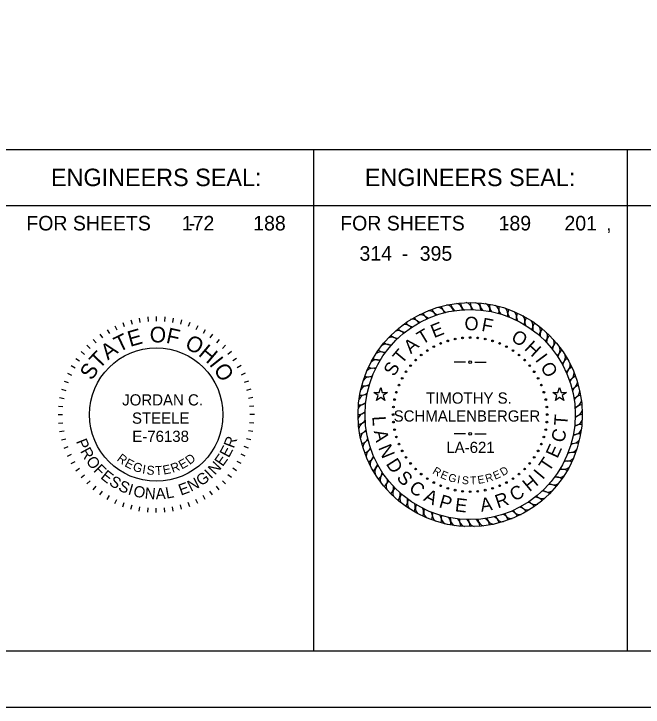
# Model space of a CAD drawing. Extents: x -42.2 to 34, y 0 to 22.
# Drawn here: x 16.1 to 21.71, y 0 to 6.19 of the extents above; entities that cross this region are included whole.
import ezdxf

# ---------------------------------------------------------------- set-up
doc = ezdxf.new("R2010")
doc.units = 0
for name, color, linetype in [('SH_Border', 7, 'Continuous'), ('SH_Cut_Line', 7, 'Continuous'), ('SH_Data', 7, 'Continuous')]:
    doc.layers.add(name, color=color, linetype=linetype)

msp = doc.modelspace()

# ---------------------------------------------------------------- linework, layer by layer
at = {"layer": 'SH_Border'}
msp.add_lwpolyline([(2, 21.5), (33.5, 21.5), (33.5, 0.5), (2, 0.5)], close=True, dxfattribs=at)
at = {"layer": 'SH_Cut_Line'}
msp.add_lwpolyline([(0, 0), (34, 0), (34, 22), (0, 22)], close=True, dxfattribs=at)
at = {"layer": 'SH_Data'}
for p, q in [((15.9739, 4.977), (18.7739, 4.977)), ((18.7739, 0.5), (18.7739, 4.977)), ((18.7739, 4.977), (21.5739, 4.977)), ((21.5739, 0.5), (21.5739, 4.977)), ((21.5739, 4.977), (24.3739, 4.977)), ((15.9739, 4.477), (18.7739, 4.477)), ((18.7739, 4.477), (21.5739, 4.477)), ((21.5739, 4.477), (24.3739, 4.477)), ((17.2172, 3.4721), (17.2242, 3.4327)), ((17.2929, 3.4821), (17.2964, 3.4422)), ((17.3692, 3.4854), (17.3692, 3.4454)), ((17.4454, 3.4821), (17.442, 3.4422)), ((17.5211, 3.4721), (17.5142, 3.4327)), ((16.9994, 3.4034), (17.0163, 3.3672)), ((17.0699, 3.4326), (17.0836, 3.395)), ((17.1427, 3.4556), (17.1531, 3.4169)), ((17.5957, 3.4556), (17.5853, 3.4169)), ((17.6685, 3.4326), (17.6548, 3.395)), ((17.739, 3.4034), (17.7221, 3.3672)), ((16.9317, 3.3682), (16.9517, 3.3335)), ((17.8067, 3.3682), (17.7867, 3.3335)), ((16.8067, 3.2807), (16.8325, 3.25)), ((16.8673, 3.3272), (16.8903, 3.2944)), ((17.8711, 3.3272), (17.8481, 3.2944)), ((17.9316, 3.2807), (17.9059, 3.25)), ((16.7505, 3.2291), (16.7788, 3.2008)), ((17.9879, 3.2291), (17.9596, 3.2008)), ((16.6989, 3.1728), (16.7295, 3.1471)), ((18.0395, 3.1728), (18.0088, 3.1471)), ((16.6524, 3.1123), (16.6852, 3.0893)), ((18.0859, 3.1123), (18.0532, 3.0893)), ((16.6114, 3.0479), (16.6461, 3.0279)), ((18.127, 3.0479), (18.0923, 3.0279)), ((20.1267, 3.0779), (20.0267, 3.0779)), ((20.2117, 3.0779), (20.3117, 3.0779)), ((16.5762, 2.9802), (16.6124, 2.9633)), ((18.1622, 2.9802), (18.126, 2.9633)), ((16.547, 2.9097), (16.5845, 2.896)), ((18.1914, 2.9097), (18.1538, 2.896)), ((16.524, 2.8369), (16.5626, 2.8265)), ((18.2144, 2.8369), (18.1757, 2.8265)), ((16.5075, 2.7623), (16.5469, 2.7554)), ((18.2309, 2.7623), (18.1915, 2.7554)), ((16.4975, 2.6867), (16.5374, 2.6832)), ((18.2409, 2.6867), (18.201, 2.6832)), ((16.4942, 2.6104), (16.5342, 2.6104)), ((18.2442, 2.6104), (18.2042, 2.6104)), ((16.4975, 2.5341), (16.5374, 2.5376)), ((18.2409, 2.5341), (18.201, 2.5376)), ((16.5075, 2.4585), (16.5469, 2.4654)), ((18.2309, 2.4585), (18.1915, 2.4654)), ((20.1267, 2.4379), (20.0267, 2.4379)), ((20.2117, 2.4379), (20.3117, 2.4379)), ((16.524, 2.3839), (16.5626, 2.3943)), ((18.2144, 2.3839), (18.1757, 2.3943)), ((16.547, 2.3111), (16.5845, 2.3248)), ((18.1914, 2.3111), (18.1538, 2.3248)), ((16.5762, 2.2406), (16.6124, 2.2575)), ((18.1622, 2.2406), (18.126, 2.2575)), ((16.6114, 2.1729), (16.6461, 2.1929)), ((18.127, 2.1729), (18.0923, 2.1929)), ((16.6524, 2.1085), (16.6852, 2.1315)), ((18.0859, 2.1085), (18.0532, 2.1315)), ((16.6989, 2.048), (16.7295, 2.0737)), ((18.0395, 2.048), (18.0088, 2.0737)), ((16.7505, 1.9917), (16.7788, 2.02)), ((17.9879, 1.9917), (17.9596, 2.02)), ((16.8067, 1.9401), (16.8325, 1.9707)), ((16.8673, 1.8936), (16.8903, 1.9264)), ((17.8711, 1.8936), (17.8481, 1.9264)), ((17.9316, 1.9401), (17.9059, 1.9707)), ((16.9317, 1.8526), (16.9517, 1.8873)), ((17.8067, 1.8526), (17.7867, 1.8873)), ((16.9994, 1.8174), (17.0163, 1.8536)), ((17.0699, 1.7882), (17.0836, 1.8258)), ((17.1427, 1.7652), (17.1531, 1.8038)), ((17.5957, 1.7652), (17.5853, 1.8038)), ((17.6685, 1.7882), (17.6548, 1.8258)), ((17.739, 1.8174), (17.7221, 1.8536)), ((17.2172, 1.7487), (17.2242, 1.7881)), ((17.2929, 1.7387), (17.2964, 1.7786)), ((17.3692, 1.7354), (17.3692, 1.7754)), ((17.4454, 1.7387), (17.442, 1.7786)), ((17.5211, 1.7487), (17.5142, 1.7881))]:
    msp.add_line(p, q, dxfattribs=at)
for points in [[(19.3097, 2.8073), (19.3566, 2.8073), (19.3711, 2.8519), (19.3856, 2.8073), (19.4324, 2.8073), (19.3946, 2.7797), (19.409, 2.7351), (19.3711, 2.7627), (19.3331, 2.7351), (19.3476, 2.7797)], [(20.9059, 2.8073), (20.9528, 2.8073), (20.9673, 2.8519), (20.9818, 2.8073), (21.0287, 2.8073), (20.9908, 2.7797), (21.0053, 2.7351), (20.9673, 2.7627), (20.9293, 2.7351), (20.9438, 2.7797)]]:
    msp.add_lwpolyline(points, close=True, dxfattribs=at)
for centre, radius in [((20.1692, 2.6104), 1), ((20.1692, 2.6104), 0.9375), ((20.0351, 3.2847), 0.0075), ((20.1018, 3.2946), 0.0075), ((20.1692, 3.2979), 0.0075), ((20.2366, 3.2946), 0.0075), ((20.3033, 3.2847), 0.0075), ((19.8451, 3.2167), 0.0075), ((19.9061, 3.2456), 0.0075), ((19.9696, 3.2683), 0.0075), ((20.3688, 3.2683), 0.0075), ((20.4323, 3.2456), 0.0075), ((20.4933, 3.2167), 0.0075), ((17.3692, 2.6104), 0.595), ((19.7872, 3.182), 0.0075), ((20.5511, 3.182), 0.0075), ((19.6831, 3.0965), 0.0075), ((19.733, 3.1418), 0.0075), ((20.6053, 3.1418), 0.0075), ((20.6553, 3.0965), 0.0075), ((19.6377, 3.0465), 0.0075), ((20.1692, 3.0779), 0.0125), ((20.7006, 3.0465), 0.0075), ((19.5976, 2.9923), 0.0075), ((20.7408, 2.9923), 0.0075), ((19.5629, 2.9345), 0.0075), ((20.7755, 2.9345), 0.0075), ((19.534, 2.8735), 0.0075), ((20.8044, 2.8735), 0.0075), ((19.5113, 2.81), 0.0075), ((20.8271, 2.81), 0.0075), ((19.4949, 2.7445), 0.0075), ((20.8435, 2.7445), 0.0075), ((19.485, 2.6778), 0.0075), ((20.8534, 2.6778), 0.0075), ((19.4817, 2.6104), 0.0075), ((20.8567, 2.6104), 0.0075), ((19.485, 2.543), 0.0075), ((20.8534, 2.543), 0.0075), ((19.4949, 2.4763), 0.0075), ((20.8435, 2.4763), 0.0075), ((19.5113, 2.4108), 0.0075), ((20.1692, 2.4379), 0.0125), ((20.8271, 2.4108), 0.0075), ((19.534, 2.3473), 0.0075), ((20.8044, 2.3473), 0.0075), ((19.5629, 2.2863), 0.0075), ((20.7755, 2.2863), 0.0075), ((19.5976, 2.2284), 0.0075), ((20.7408, 2.2284), 0.0075), ((19.6377, 2.1742), 0.0075), ((20.7006, 2.1742), 0.0075), ((19.6831, 2.1243), 0.0075), ((20.6553, 2.1243), 0.0075), ((19.733, 2.0789), 0.0075), ((19.7872, 2.0388), 0.0075), ((20.5511, 2.0388), 0.0075), ((20.6053, 2.0789), 0.0075), ((19.8451, 2.0041), 0.0075), ((19.9061, 1.9752), 0.0075), ((20.4323, 1.9752), 0.0075), ((20.4933, 2.0041), 0.0075), ((19.9696, 1.9525), 0.0075), ((20.0351, 1.9361), 0.0075), ((20.1018, 1.9262), 0.0075), ((20.1692, 1.9229), 0.0075), ((20.2366, 1.9262), 0.0075), ((20.3033, 1.9361), 0.0075), ((20.3688, 1.9525), 0.0075)]:
    msp.add_circle(centre, radius, dxfattribs=at)
for centre, radius, start, end in [((19.9567, 3.5235), 0.065, 11.11471, 86.62222), ((20.0792, 3.61), 0.085, 190, 237.74501), ((20.0371, 3.5385), 0.065, 6.11471, 81.62222), ((20.1667, 3.614), 0.085, 185, 232.74501), ((20.1185, 3.5465), 0.065, 1.11471, 76.62222), ((20.2542, 3.6104), 0.085, 180, 227.74501), ((20.2002, 3.5474), 0.065, 356.11471, 71.62222), ((20.341, 3.5992), 0.085, 175, 222.74501), ((20.2818, 3.5411), 0.065, 351.11471, 66.62222), ((20.4265, 3.5804), 0.085, 170, 217.74501), ((19.8014, 3.4727), 0.065, 21.11471, 96.62222), ((19.907, 3.5792), 0.085, 200, 247.74501), ((19.8779, 3.5015), 0.065, 16.11471, 91.62222), ((19.9925, 3.5983), 0.085, 195, 242.74501), ((20.3625, 3.5278), 0.065, 346.11471, 61.62222), ((20.5101, 3.5543), 0.085, 165, 212.74501), ((20.4417, 3.5074), 0.065, 341.11471, 56.62222), ((20.5911, 3.521), 0.085, 160, 207.74501), ((20.5188, 3.4802), 0.065, 336.11471, 51.62222), ((19.7428, 3.5189), 0.085, 210, 257.74501), ((19.7276, 3.4374), 0.065, 26.11471, 101.62222), ((19.8236, 3.5526), 0.085, 205, 252.74501), ((20.6688, 3.4808), 0.085, 155, 202.74501), ((20.5933, 3.4465), 0.065, 331.11471, 46.62222), ((20.7428, 3.4339), 0.085, 150, 197.74501), ((19.5907, 3.3481), 0.065, 36.11471, 111.62222), ((19.6652, 3.4783), 0.085, 215, 262.74501), ((19.6572, 3.3957), 0.065, 31.11471, 106.62222), ((20.6646, 3.4063), 0.065, 326.11471, 41.62222), ((20.8124, 3.3808), 0.085, 145, 192.74501), ((19.5286, 3.2949), 0.065, 41.11471, 116.62222), ((19.5915, 3.4311), 0.085, 220, 267.74501), ((20.7321, 3.3601), 0.065, 321.11471, 36.62222), ((20.8771, 3.3218), 0.085, 140, 187.74501), ((20.7953, 3.3082), 0.065, 316.11471, 31.62222), ((19.4714, 3.2365), 0.065, 46.11471, 121.62222), ((19.5222, 3.3776), 0.085, 225, 272.74501), ((20.9364, 3.2574), 0.085, 135, 182.74501), ((20.8537, 3.251), 0.065, 311.11471, 26.62222), ((19.4195, 3.1733), 0.065, 51.11471, 126.62222), ((19.4578, 3.3183), 0.085, 230, 277.74501), ((20.9899, 3.1881), 0.085, 130, 177.74501), ((19.3733, 3.1058), 0.065, 56.11471, 131.62222), ((19.3988, 3.2536), 0.085, 235, 282.74501), ((20.9069, 3.1889), 0.065, 306.11471, 21.62222), ((21.0371, 3.1143), 0.085, 125, 172.74501), ((19.3331, 3.0345), 0.065, 61.11471, 136.62222), ((19.3457, 3.184), 0.085, 240, 287.74501), ((20.9545, 3.1224), 0.065, 301.11471, 16.62222), ((21.0777, 3.0368), 0.085, 120, 167.74501), ((19.2988, 3.11), 0.085, 245, 292.74501), ((20.9962, 3.052), 0.065, 296.11471, 11.62222), ((21.1114, 2.956), 0.085, 115, 162.74501), ((19.2993, 2.96), 0.065, 66.11471, 141.62222), ((21.0315, 2.9782), 0.065, 291.11471, 6.62222), ((19.2722, 2.8829), 0.065, 71.11471, 146.62222), ((19.2586, 3.0323), 0.085, 250, 297.74501), ((21.138, 2.8725), 0.085, 110, 157.74501), ((19.2518, 2.8037), 0.065, 76.11471, 151.62222), ((19.2253, 2.9513), 0.085, 255, 302.74501), ((21.0603, 2.9017), 0.065, 286.11471, 1.62222), ((21.1571, 2.7871), 0.085, 105, 152.74501), ((19.2385, 2.723), 0.065, 81.11471, 156.62222), ((19.1991, 2.8678), 0.085, 260, 307.74501), ((21.0823, 2.8229), 0.065, 281.11471, 356.62222), ((21.1688, 2.7003), 0.085, 100, 147.74501), ((21.0973, 2.7425), 0.065, 276.11471, 351.62222), ((19.2322, 2.6415), 0.065, 86.11471, 161.62222), ((19.1804, 2.7822), 0.085, 265, 312.74501), ((21.1728, 2.6129), 0.085, 95, 142.74501), ((19.1692, 2.6954), 0.085, 270, 317.74501), ((19.2331, 2.5597), 0.065, 91.11471, 166.62222), ((21.1692, 2.5254), 0.085, 90, 137.74501), ((21.1053, 2.6611), 0.065, 271.11471, 346.62222), ((19.1656, 2.6079), 0.085, 275, 322.74501), ((19.241, 2.4783), 0.065, 96.11471, 171.62222), ((21.1062, 2.5793), 0.065, 266.11471, 341.62222), ((19.1696, 2.5205), 0.085, 280, 327.74501), ((21.158, 2.4386), 0.085, 85, 132.74501), ((19.2561, 2.3979), 0.065, 101.11471, 176.62222), ((21.1392, 2.353), 0.085, 80, 127.74501), ((21.0999, 2.4978), 0.065, 261.11471, 336.62222), ((19.1813, 2.4337), 0.085, 285, 332.74501), ((19.2781, 2.3191), 0.065, 106.11471, 181.62222), ((21.1131, 2.2695), 0.085, 75, 122.74501), ((21.0865, 2.4171), 0.065, 256.11471, 331.62222), ((19.2004, 2.3482), 0.085, 290, 337.74501), ((19.3069, 2.2426), 0.065, 111.11471, 186.62222), ((21.0662, 2.3379), 0.065, 251.11471, 326.62222), ((19.227, 2.2648), 0.085, 295, 342.74501), ((19.3422, 2.1688), 0.065, 116.11471, 191.62222), ((21.0798, 2.1885), 0.085, 70, 117.74501), ((19.2607, 2.184), 0.085, 300, 347.74501), ((21.0396, 2.1107), 0.085, 65, 112.74501), ((21.039, 2.2607), 0.065, 246.11471, 321.62222), ((19.3838, 2.0984), 0.065, 121.11471, 196.62222), ((20.9927, 2.0368), 0.085, 60, 107.74501), ((21.0053, 2.1863), 0.065, 241.11471, 316.62222), ((19.3013, 2.1064), 0.085, 305, 352.74501), ((19.4314, 2.0319), 0.065, 126.11471, 201.62222), ((20.9396, 1.9672), 0.085, 55, 102.74501), ((20.9651, 2.115), 0.065, 236.11471, 311.62222), ((19.3485, 2.0327), 0.085, 310, 357.74501), ((19.4847, 1.9698), 0.065, 131.11471, 206.62222), ((20.8806, 1.9025), 0.085, 50, 97.74501), ((20.9189, 2.0475), 0.065, 231.11471, 306.62222), ((19.402, 1.9634), 0.085, 315, 2.74501), ((19.5431, 1.9126), 0.065, 136.11471, 211.62222), ((20.8162, 1.8432), 0.085, 45, 92.74501), ((20.867, 1.9843), 0.065, 226.11471, 301.62222), ((19.4613, 1.899), 0.085, 320, 7.74501), ((19.6063, 1.8607), 0.065, 141.11471, 216.62222), ((19.526, 1.84), 0.085, 325, 12.74501), ((20.7469, 1.7897), 0.085, 40, 87.74501), ((20.8098, 1.9259), 0.065, 221.11471, 296.62222), ((19.6738, 1.8145), 0.065, 146.11471, 221.62222), ((19.5956, 1.7869), 0.085, 330, 17.74501), ((19.745, 1.7743), 0.065, 151.11471, 226.62222), ((20.6731, 1.7425), 0.085, 35, 82.74501), ((20.7477, 1.8727), 0.065, 216.11471, 291.62222), ((19.6695, 1.74), 0.085, 335, 22.74501), ((19.8195, 1.7405), 0.065, 156.11471, 231.62222), ((19.7473, 1.6998), 0.085, 340, 27.74501), ((19.8967, 1.7134), 0.065, 161.11471, 236.62222), ((20.5148, 1.6682), 0.085, 25, 72.74501), ((20.6108, 1.7834), 0.065, 206.11471, 281.62222), ((20.5956, 1.7019), 0.085, 30, 77.74501), ((20.6812, 1.825), 0.065, 211.11471, 286.62222), ((19.8283, 1.6665), 0.085, 345, 32.74501), ((19.9759, 1.693), 0.065, 166.11471, 241.62222), ((19.9118, 1.6403), 0.085, 350, 37.74501), ((20.0566, 1.6797), 0.065, 171.11471, 246.62222), ((19.9974, 1.6216), 0.085, 355, 42.74501), ((20.1381, 1.6734), 0.065, 176.11471, 251.62222), ((20.0842, 1.6104), 0.085, 360, 47.74501), ((20.2199, 1.6743), 0.065, 181.11471, 256.62222), ((20.1717, 1.6068), 0.085, 5, 52.74501), ((20.3013, 1.6823), 0.065, 186.11471, 261.62222), ((20.2591, 1.6108), 0.085, 10, 57.74501), ((20.3817, 1.6973), 0.065, 191.11471, 266.62222), ((20.3459, 1.6225), 0.085, 15, 62.74501), ((20.4605, 1.7193), 0.065, 196.11471, 271.62222), ((20.4313, 1.6416), 0.085, 20, 67.74501), ((20.537, 1.7481), 0.065, 201.11471, 276.62222)]:
    msp.add_arc(centre, radius, start, end, dxfattribs=at)

# ---------------------------------------------------------------- texts
for s, height, p in [('ENGINEERS SEAL:', 0.156, (16.4298, 4.649)), ('ENGINEERS SEAL:', 0.156, (19.2298, 4.649)), ('FOR SHEETS       -', 0.13, (16.2104, 4.2535)), ('172', 0.13, (17.5972, 4.2535)), ('188', 0.13, (18.2342, 4.2535)), ('FOR SHEETS       -', 0.13, (19.0104, 4.2535)), ('189', 0.13, (20.423, 4.2535)), ('201', 0.13, (21.0103, 4.2535)), (',', 0.13, (21.3824, 4.2535)), ('314', 0.13, (19.182, 3.9835)), ('395', 0.13, (19.7193, 3.9835)), ('-', 0.13, (19.5582, 3.9835)), ('JORDAN C.', 0.1, (17.0655, 2.6916)), ('TIMOTHY S.', 0.1, (19.7755, 2.7079)), ('STEELE', 0.1, (17.1527, 2.5291)), ('SCHMALENBERGER', 0.1, (19.4868, 2.5479)), ('E-76138', 0.1, (17.1553, 2.3666)), ('LA-621', 0.1, (19.9568, 2.2679))]:
    msp.add_text(s, height=height, dxfattribs=at).set_placement(p)
for s, height, rotation, p in [('O', 0.12, 0.29633, (20.1195, 3.3626)), ('F', 0.12, 349.24037, (20.2647, 3.3582)), ('E', 0.12, 21.84382, (19.8467, 3.2918)), ('E', 0.14, 15.75706, (17.1361, 3.2138)), ('O', 0.14, 359.78119, (17.3112, 3.2546)), ('F', 0.14, 347.43619, (17.4503, 3.2521)), ('T', 0.12, 31.15002, (19.7407, 3.2307)), ('O', 0.12, 328.27849, (20.5259, 3.2746)), ('T', 0.14, 25.71674, (17.0353, 3.1644)), ('O', 0.14, 332.25863, (17.6154, 3.2085)), ('A', 0.12, 41.04183, (19.6405, 3.1479)), ('A', 0.14, 36.47472, (16.9377, 3.0923)), ('H', 0.14, 319.91363, (17.7376, 3.142)), ('H', 0.12, 317.22252, (20.6466, 3.1938)), ('T', 0.14, 46.4344, (16.8609, 3.0104)), ('T', 0.12, 50.34803, (19.5606, 3.0553)), ('I', 0.12, 306.75216, (20.7447, 3.0974)), ('I', 0.14, 308.36695, (17.8366, 3.0575)), ('S', 0.14, 57.19238, (16.7952, 2.9085)), ('O', 0.14, 303.14906, (17.8753, 3.0132)), ('S', 0.12, 60.23983, (19.4932, 2.9441)), ('O', 0.12, 300.92432, (20.7912, 3.0364)), ('T', 0.12, 85.83012, (21.0366, 2.5088)), ('L', 0.12, 273.59838, (19.296, 2.5938)), ('C', 0.12, 75.35976, (21.0037, 2.3529)), ('R', 0.1, 69.23216, (18.0605, 2.304)), ('A', 0.12, 282.33309, (19.3087, 2.4614)), ('P', 0.1, 291.49398, (16.6515, 2.3722)), ('E', 0.12, 65.46796, (20.9471, 2.2134)), ('R', 0.1, 298.73106, (16.6873, 2.2837)), ('E', 0.1, 61.99508, (18.0164, 2.2194)), ('N', 0.12, 292.2249, (19.3471, 2.3158)), ('O', 0.1, 306.46664, (16.7374, 2.1949)), ('R', 0.08, 323.2378, (17.012, 2.2045)), ('D', 0.08, 38.0378, (17.6673, 2.1592)), ('E', 0.1, 54.75801, (17.9619, 2.141)), ('T', 0.12, 56.16176, (20.8726, 2.0928)), ('F', 0.1, 314.7068, (16.8035, 2.1087)), ('E', 0.08, 332.42558, (17.0814, 2.1526)), ('G', 0.08, 341.00757, (17.1529, 2.1148)), ('E', 0.08, 11.68604, (17.436, 2.0738)), ('R', 0.08, 20.26803, (17.5154, 2.0898)), ('E', 0.08, 29.45581, (17.5966, 2.1198)), ('N', 0.1, 47.02243, (17.8934, 2.0654)), ('D', 0.12, 302.69525, (19.4143, 2.1713)), ('E', 0.1, 321.43929, (16.8662, 2.0458)), ('I', 0.08, 350.80853, (17.2404, 2.0852)), ('S', 0.08, 355.13523, (17.2804, 2.077)), ('T', 0.08, 3.71722, (17.361, 2.0697)), ('I', 0.1, 43.28703, (17.8567, 2.0324)), ('S', 0.12, 313.16561, (19.5067, 2.0414)), ('R', 0.07, 329.4323, (19.8277, 2.0891)), ('E', 0.07, 336.81551, (19.8975, 2.0496)), ('E', 0.07, 23.59245, (20.3918, 2.0283)), ('D', 0.07, 30.5677, (20.4608, 2.0597)), ('I', 0.12, 50.33391, (20.8164, 2.024)), ('S', 0.1, 328.67637, (16.9413, 1.9869)), ('N', 0.1, 27.31129, (17.6788, 1.9206)), ('G', 0.1, 35.04687, (17.7689, 1.9685)), ('G', 0.07, 343.79076, (19.9676, 2.0207)), ('I', 0.07, 351.58692, (20.0495, 1.9988)), ('S', 0.07, 355.69644, (20.0936, 1.9918)), ('T', 0.07, 2.67169, (20.1693, 1.9872)), ('E', 0.07, 9.23399, (20.2405, 1.9913)), ('R', 0.07, 16.20924, (20.3152, 2.0046)), ('H', 0.12, 39.86356, (20.6991, 1.9162)), ('S', 0.1, 335.91345, (17.0233, 1.938)), ('I', 0.1, 343.15053, (17.1108, 1.8998)), ('E', 0.1, 20.07421, (17.5895, 1.8871)), ('C', 0.12, 323.05742, (19.6143, 1.936)), ('O', 0.1, 346.88592, (17.1576, 1.8845)), ('N', 0.1, 355.12608, (17.2638, 1.8616)), ('A', 0.1, 2.86166, (17.3656, 1.8543)), ('L', 0.1, 10.09874, (17.4608, 1.8598)), ('A', 0.12, 333.52778, (19.746, 1.8464)), ('C', 0.12, 29.3932, (20.5641, 1.8314)), ('P', 0.12, 343.41958, (19.8836, 1.7851)), ('E', 0.12, 353.31139, (20.0296, 1.7483)), ('A', 0.12, 9.03104, (20.2684, 1.7427)), ('R', 0.12, 18.92284, (20.416, 1.7727))]:
    msp.add_text(s, height=height, rotation=rotation, dxfattribs=at).set_placement(p)

doc.saveas('drawing.dxf')
